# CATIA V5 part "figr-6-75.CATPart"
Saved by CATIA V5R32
Part number: Part1
Bounding box of the stored display mesh (mm): x 0 to 80, y -59 to 59, z -11 to 11
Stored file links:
  D:\PROJECTS\Project 2022\CATIA V5 6R 2022\Resources\Part Files\c06_catia_v5_6r2022_prt\figr-6-75.CATPart
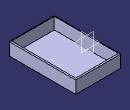
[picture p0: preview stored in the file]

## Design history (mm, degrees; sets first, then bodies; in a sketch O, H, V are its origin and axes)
Body1 (main body)
  Sketch1 on yz-plane, origin (0, 0, 0), H (0, 1, 0), V (0, 0, 1)
    line L1 (59, 11) -> (59, -11)
    line L2 (59, -11) -> (-59, -11)
    line L3 (-59, -11) -> (-59, 11)
    line L4 (-59, 11) -> (59, 11)
    vertical: L1 V, L3 V
    horizontal: L2 H, L4 H
    equidistance: L1 L3 O, L2 L4 O
  Pad1: profile Sketch1, direction (1, 0, 0), length 80
  Shell1: ExtOffset 0, Face face of Pad1 from Sketch1.L4, IntOffset 1, ShellSkin (ExtOffset 0, InitFace end face of Pad1, IntOffset 3; ExtOffset 0, InitFace face of Pad1 from Sketch1.L1, IntOffset 3)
